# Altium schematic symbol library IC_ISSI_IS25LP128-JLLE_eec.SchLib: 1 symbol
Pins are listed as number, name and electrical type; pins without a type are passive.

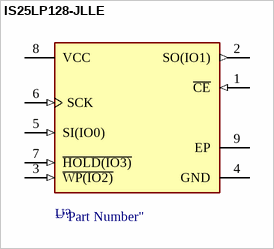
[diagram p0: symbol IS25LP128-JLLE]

## IS25LP128-JLLE
designator U?  (value not drawn)
pins: 1 ~{CE} (in), 2 SO(IO1) (out), 3 ~{WP(IO2)} (in), 4 GND (power), 5 SI(IO0) (in), 6 SCK (in), 7 ~{HOLD(IO3)} (in), 8 VCC (power), 9 EP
